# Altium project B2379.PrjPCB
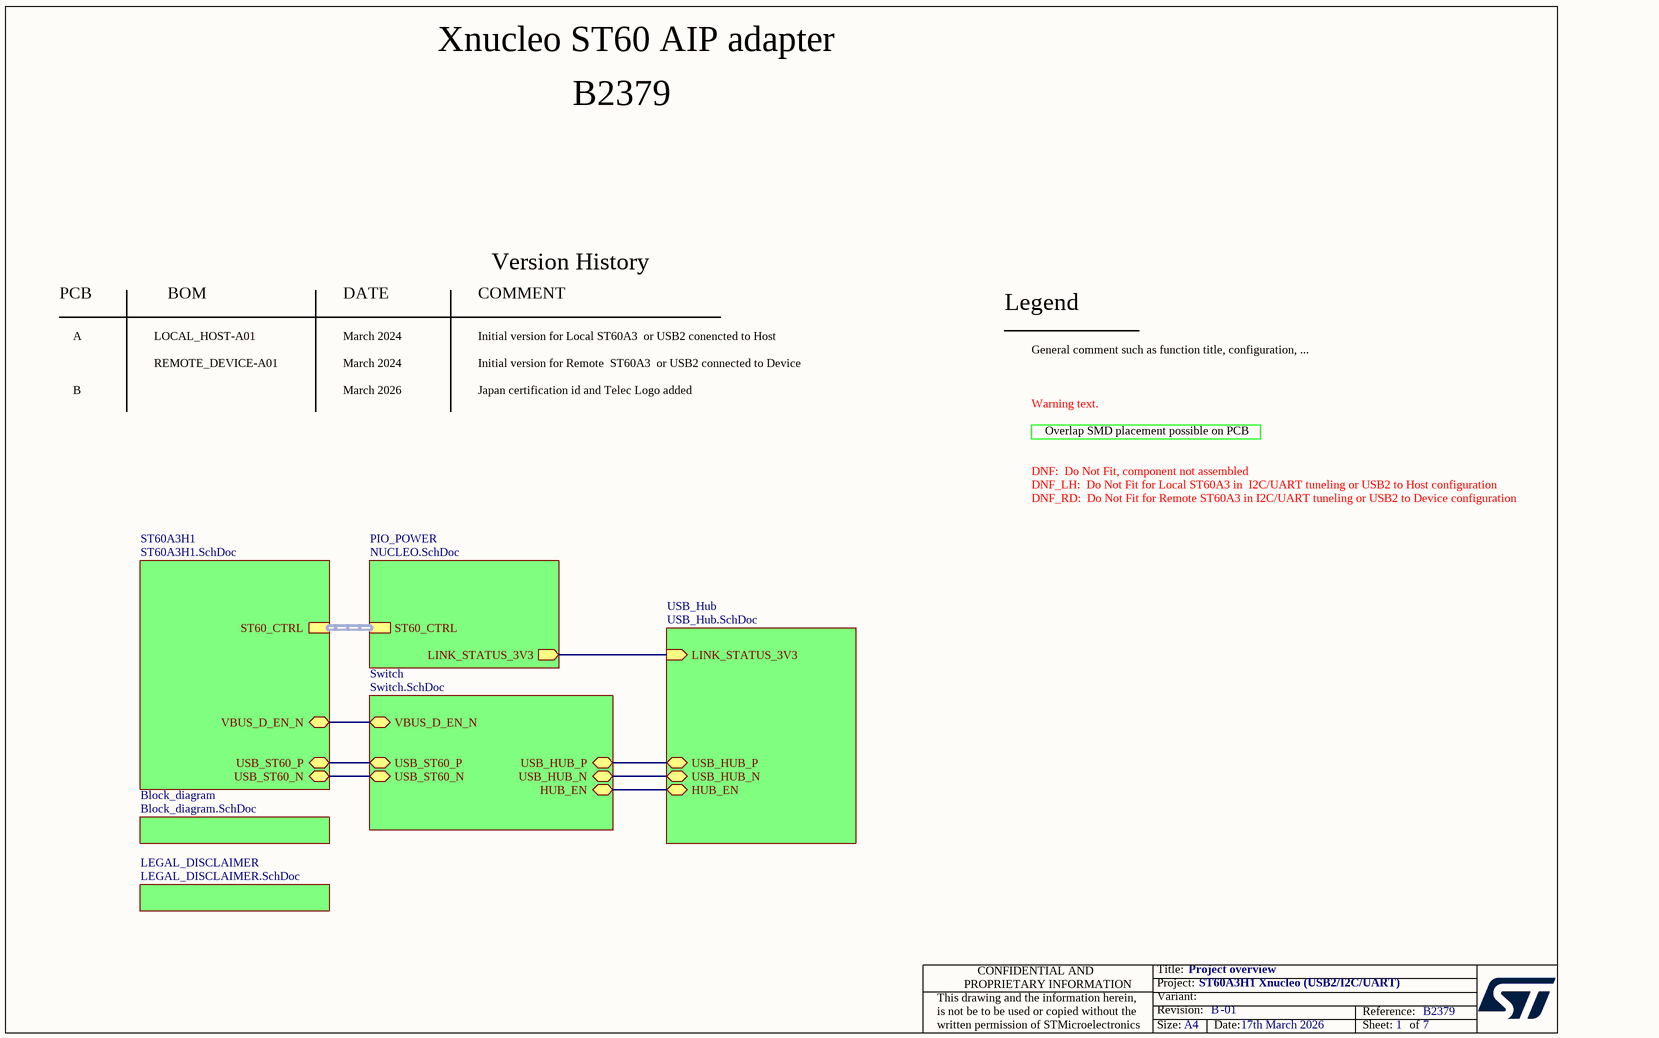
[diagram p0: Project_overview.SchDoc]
Board_Assembly_Revision: 01; Board_Document_Date: 17th March 2026; Board_Name: ST60A3H1 Xnucleo (USB2/I2C/UART); Board_PCB_Revision: B; Board_Reference: B2379
7 sheets, 182 parts. Net scope: hierarchical (ports join the sheet entries above them; power ports are global).
Board file: B2379.PcbDoc
Sheets:
  Project_overview.SchDoc
    ST60A3H1 = ST60A3H1.SchDoc
    Block_diagram = Block_diagram.SchDoc
    PIO_POWER = NUCLEO.SchDoc
    USB_Hub = USB_Hub.SchDoc
    LEGAL_DISCLAIMER = LEGAL_DISCLAIMER.SchDoc
    Switch = Switch.SchDoc

## Sheet Project_overview.SchDoc: Project overview
size A4; Date: Not used; ApprovedBy: Not used; CheckedBy: Not used; Author: Not used; CompanyName: STMicroelectronics; DrawnBy: Not used; Engineer: Not used; Organization: Not used; Address1: Not used; Address2: Not used; Address3: Not used; Address4: Not used; DocumentNumber: 1; Revision: Not used; SheetNumber: 1; SheetTotal: 7

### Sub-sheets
Block_diagram = Block_diagram.SchDoc: no entries
LEGAL_DISCLAIMER = LEGAL_DISCLAIMER.SchDoc: no entries
PIO_POWER = NUCLEO.SchDoc: ST60_CTRL (harness ST60_CTRL), LINK_STATUS_3V3 (out)
ST60A3H1 = ST60A3H1.SchDoc: USB_ST60_P (bidir), USB_ST60_N (bidir), ST60_CTRL (harness ST60_CTRL), VBUS_D_EN_N (bidir)
Switch = Switch.SchDoc: USB_ST60_P (bidir), USB_ST60_N (bidir), USB_HUB_N (bidir), USB_HUB_P (bidir), VBUS_D_EN_N (bidir), HUB_EN (bidir)
USB_Hub = USB_Hub.SchDoc: LINK_STATUS_3V3 (in), USB_HUB_N (bidir), USB_HUB_P (bidir), HUB_EN (bidir)

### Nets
HUB_EN: sheet USB_Hub/HUB_EN, sheet Switch/HUB_EN
LINK_STATUS_3V3: sheet PIO_POWER/LINK_STATUS_3V3, sheet USB_Hub/LINK_STATUS_3V3
USB_HUB_N: sheet USB_Hub/USB_HUB_N, sheet Switch/USB_HUB_N
USB_HUB_P: sheet USB_Hub/USB_HUB_P, sheet Switch/USB_HUB_P
USB_ST60_N: sheet ST60A3H1/USB_ST60_N, sheet Switch/USB_ST60_N
USB_ST60_P: sheet ST60A3H1/USB_ST60_P, sheet Switch/USB_ST60_P
VBUS_D_EN_N: sheet ST60A3H1/VBUS_D_EN_N, sheet Switch/VBUS_D_EN_N

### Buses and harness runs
harness sheet PIO_POWER/ST60_CTRL = sheet ST60A3H1/ST60_CTRL

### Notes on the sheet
- Xnucleo ST60 AIP adapter
- PCB
- BOM
- DATE
- COMMENT
- Version History
- Legend
- A
- LOCAL_HOST-A01
- REMOTE_DEVICE-A01
- March 2024
- Initial version for Local ST60A3  or USB2 conencted to Host
- Initial version for Remote  ST60A3  or USB2 connected to Device
- General comment such as function title, configuration, ...
- B
- March 2026
- Japan certification id and Telec Logo added
- Warning text.
- Overlap SMD placement possible on PCB
- DNF:  Do Not Fit, component not assembled
- DNF_LH:  Do Not Fit for Local ST60A3 in  I2C/UART tuneling or USB2 to Host configuration
- DNF_RD:  Do Not Fit for Remote ST60A3 in I2C/UART tuneling or USB2 to Device configuration

## Sheet ST60A3H1.SchDoc: ST60A3H1
size A4; DocumentNumber: 3; SheetNumber: 3; SheetTotal: 7
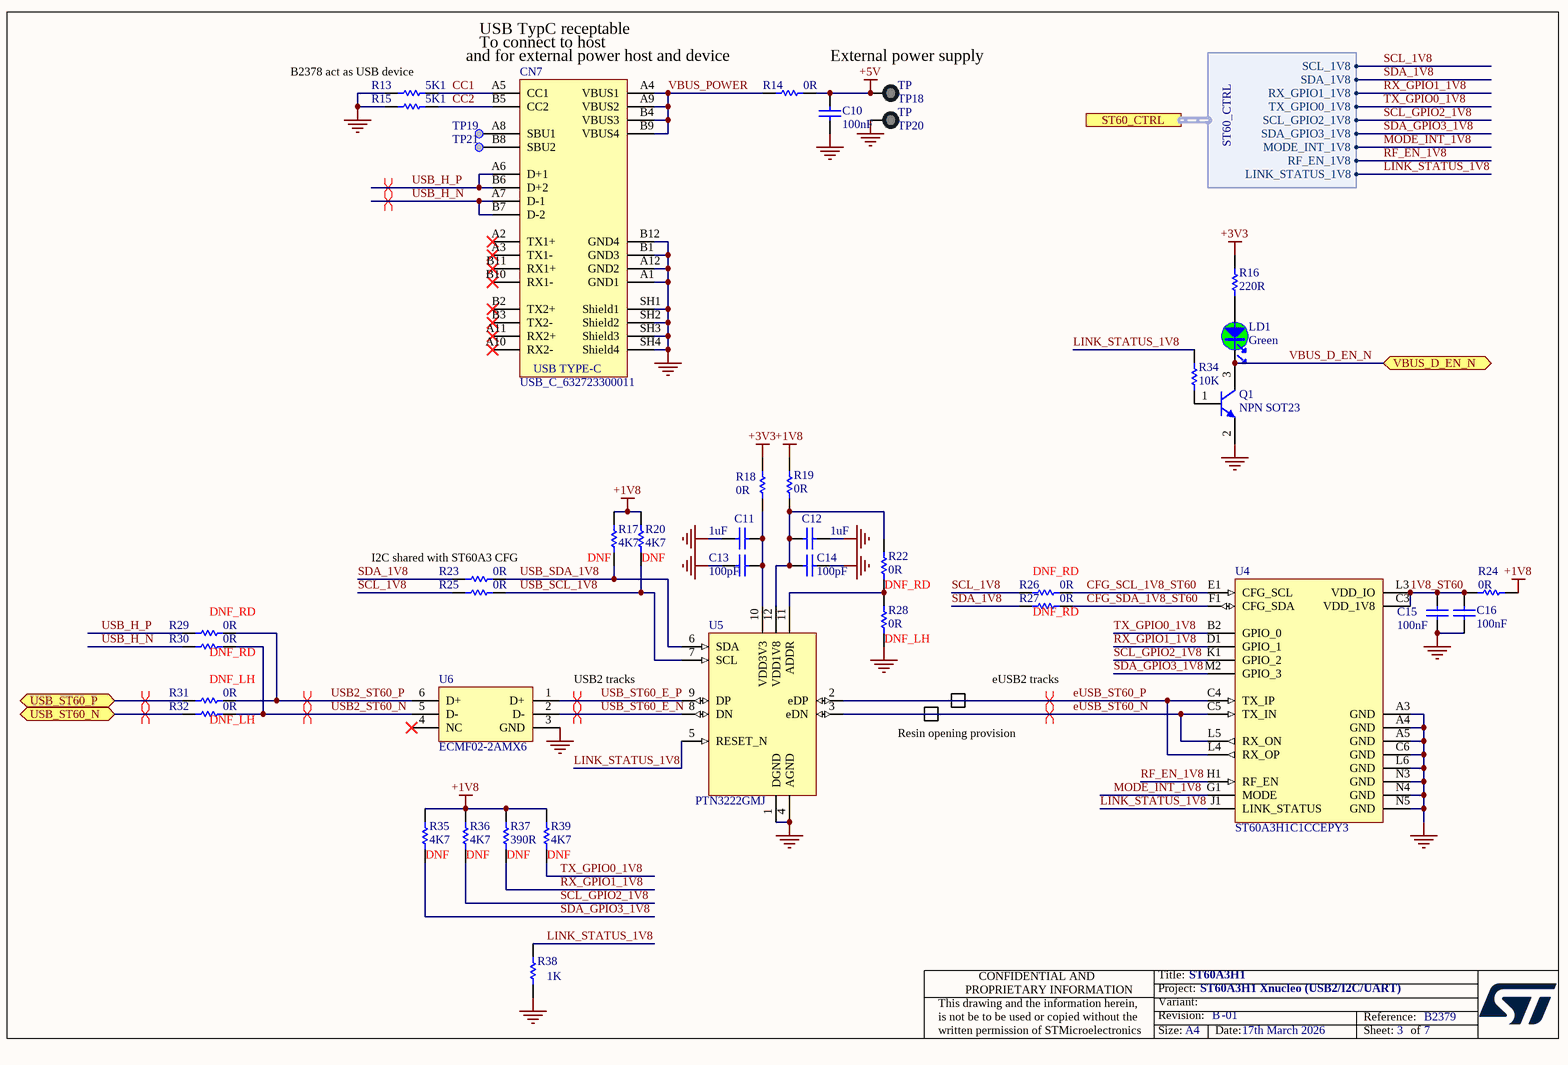
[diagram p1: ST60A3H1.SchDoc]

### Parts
C10  value 100nF  [C0402]  (hidden comment: Capacitor)
C11  value 1uF  [C0402]  (hidden comment: Capacitor)
C12  value 1uF  [C0402]  (hidden comment: Capacitor)
C13  value 100pF  [C0402]  (hidden comment: Capacitor)
C14  value 100pF  [C0402]  (hidden comment: Capacitor)
C15  value 100nF  [C0402]  (hidden comment: Capacitor)
C16  value 100nF  [C0402]  (hidden comment: Capacitor)
CN7  value USB_C_632723300011  [CON_USB-TYPEC_WE_632723300011]  (hidden comment: USB_TYPE_C_Receptacle)
LD1  value Green  [LED_0603_GREEN]  (hidden comment: LED_green)
Q1  value NPN SOT23  [NPN_SOT23]  (hidden comment: 9013-SOT23)
R13  value 5K1  [R0402]  (hidden comment: Resistor)
R14  value 0R  [SOLDER-BRIDGE_R0603-0R]  (hidden comment: Resistor)
R15  value 5K1  [R0402]  (hidden comment: Resistor)
R16  value 220R  [R0402]  (hidden comment: Resistor)
R17  value 4K7  [R0402]  (hidden comment: Resistor)
R18  value 0R  [R0402]  (hidden comment: Resistor)
R19  value 0R  [R0402]  (hidden comment: Resistor)
R20  value 4K7  [R0402]  (hidden comment: Resistor)
R22  value 0R  [SOLDER-BRIDGE_R0603-0R]  (hidden comment: Resistor)
R23  value 0R  [R0402]  (hidden comment: Resistor)
R24  value 0R  [R0402]  (hidden comment: Resistor)
R25  value 0R  [R0402]  (hidden comment: Resistor)
R26  value 0R  [SOLDER-BRIDGE_R0603-0R]  (hidden comment: Resistor)
R27  value 0R  [SOLDER-BRIDGE_R0603-0R]  (hidden comment: Resistor)
R28  value 0R  [SOLDER-BRIDGE_R0603-0R]  (hidden comment: Resistor)
R29  value 0R  [R0402_BGA]  (hidden comment: Resistor)
R30  value 0R  [R0402_BGA]  (hidden comment: Resistor)
R31  value 0R  [R0402_BGA]  (hidden comment: Resistor)
R32  value 0R  [R0402_BGA]  (hidden comment: Resistor)
R34  value 10K  [R0402]  (hidden comment: Resistor)
R35  value 4K7  [R0402]  (hidden comment: Resistor)
R36  value 4K7  [R0402]  (hidden comment: Resistor)
R37  value 390R  [R0402]  (hidden comment: Resistor)
R38  value 1K  [R0402]  (hidden comment: Resistor)
R39  value 4K7  [R0402]  (hidden comment: Resistor)
TP18  value TP  [TP_PTH_1MM_1P4MM]  (hidden comment: Test_Point_PTH_1mm_2mm)  (no BOM)
TP19  Test Point  [TP_SMD_1MM]  (value not drawn)  (no BOM)
TP20  value TP  [TP_PTH_1MM_1P4MM]  (hidden comment: Test_Point_PTH_1mm_2mm)  (no BOM)
TP21  Test Point  [TP_SMD_1MM]  (value not drawn)  (no BOM)
U4  value ST60A3H1C1CCEPY3  [ICC_VFBGA23_AiP_2P9X4P1_P040_B2310D]  (hidden comment: ST60A3G1)
U5  PTN3222GMJ  [ICC_XQFN12_1P75X2P2_P040_SOT2074-1]
U6  value ECMF02-2AMX6  [ESD_QFN-6L_1P7X1P5_P050]  (hidden comment: ​)

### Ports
ST60_CTRL (harness ST60_CTRL), USB_ST60_N (bidir), USB_ST60_P (bidir), VBUS_D_EN_N (bidir)

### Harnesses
ST60_CTRL: SCL_1V8, SDA_1V8, TX_GPIO0_1V8, RX_GPIO1_1V8, SCL_GPIO2_1V8, SDA_GPIO3_1V8, MODE_INT_1V8, RF_EN_1V8, LINK_STATUS_1V8

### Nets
+1V8: R17.2 R19.2 R20.2 R24.1 R35.2 R36.2 R37.2 R39.2
+3V3: R16.2 R18.2
+5V: C10.2 R14.2 TP18.1
GND: C10.1 C11.1 C12.2 C13.2 C14.2 C15.1 C16.2 CN7.A1(GND1) CN7.A12(GND2) CN7.B1(GND3) CN7.B12(GND4) CN7.SH1(Shield1) CN7.SH2(Shield2) CN7.SH3(Shield3) CN7.SH4(Shield4) Q1.2(E) R13.1 R15.1 R28.2 R38.1 TP20.1 U4.A3(GND) U4.A4(GND) U4.A5(GND) U4.C6(GND) U4.L6(GND) U4.N3(GND) U4.N4(GND) U4.N5(GND) U5.1(DGND) U5.4(AGND) U6.3(GND)
1V8_ST60: C15.2 C16.1 R24.2 U4.C3(VDD_1V8) U4.L3(VDD_IO)  [project net 1V8_ST60_3]
CC1: CN7.A5(CC1) R13.2  [project net CC1_3]
CC2: CN7.B5(CC2) R15.2  [project net CC2_3]
CFG_SCL_1V8_ST60: R26.2 U4.E1(CFG_SCL)  [project net CFG_SCL_1V8_ST60_3]
CFG_SDA_1V8_ST60: R27.2 U4.F1(CFG_SDA)  [project net CFG_SDA_1V8_ST60_3]
eUSB_ST60_N: U4.C5(TX_IN) U4.L5(RX_ON) U5.3(eDN)  [project net eUSB_ST60_N_3]
eUSB_ST60_P: U4.C4(TX_IP) U4.L4(RX_OP) U5.2(eDP)  [project net eUSB_ST60_P_3]
LINK_STATUS_1V8: R34.2 R38.2 U4.J1(LINK_STATUS) U5.5(RESET_N) ; port ST60_CTRL.LINK_STATUS_1V8
MODE_INT_1V8: U4.G1(MODE) ; port ST60_CTRL.MODE_INT_1V8
RF_EN_1V8: U4.H1(RF_EN) ; port ST60_CTRL.RF_EN_1V8
RX_GPIO1_1V8: R37.1 U4.D1(GPIO_1) ; port ST60_CTRL.RX_GPIO1_1V8
SCL_1V8: R25.1 R26.1 ; port ST60_CTRL.SCL_1V8
SCL_GPIO2_1V8: R36.1 U4.K1(GPIO_2) ; port ST60_CTRL.SCL_GPIO2_1V8
SDA_1V8: R23.1 R27.1 ; port ST60_CTRL.SDA_1V8
SDA_GPIO3_1V8: R35.1 U4.M2(GPIO_3) ; port ST60_CTRL.SDA_GPIO3_1V8
TX_GPIO0_1V8: R39.1 U4.B2(GPIO_0) ; port ST60_CTRL.TX_GPIO0_1V8
USB2_ST60_N: R30.2 R32.2 U6.5(D-)  [project net USB2_ST60_N_3]
USB2_ST60_P: R29.2 R31.2 U6.6(D+)  [project net USB2_ST60_P_3]
USB_H_N: CN7.A7(D-1) CN7.B7(D-2) R30.1  [project net USB_H_N_3]
USB_H_P: CN7.A6(D+1) CN7.B6(D+2) R29.1  [project net USB_H_P_3]
USB_SCL_1V8: R20.1 R25.2 U5.7(SCL)  [project net USB_SCL_1V8_3]
USB_SDA_1V8: R17.1 R23.2 U5.6(SDA)  [project net USB_SDA_1V8_3]
USB_ST60_E_N: U5.8(DN) U6.2(D-)  [project net USB_ST60_E_N_3]
USB_ST60_E_P: U5.9(DP) U6.1(D+)  [project net USB_ST60_E_P_3]
USB_ST60_N: R32.1 ; port USB_ST60_N
USB_ST60_P: R31.1 ; port USB_ST60_P
VBUS_D_EN_N: LD1.2 Q1.3(C) ; port VBUS_D_EN_N
VBUS_POWER: CN7.A4(VBUS1) CN7.A9(VBUS2) CN7.B4(VBUS3) CN7.B9(VBUS4) R14.1  [project net VBUS_POWER_3]
NetC11_2: C11.2 C13.1 R18.1 U5.10(VDD3V3)
NetC12_1: C12.1 C14.1 R19.1 R22.1 U5.12(VDD1V8)
NetCN7_A8: CN7.A8(SBU1) TP19.1
NetCN7_B8: CN7.B8(SBU2) TP21.1
NetLD1_1: LD1.1 R16.1
NetQ1_1: Q1.1(B) R34.1
NetR22_2: R22.2 R28.1 U5.11(ADDR)

Not connected (* = marked no-connect by the designer): CN7 A2(TX1+)* A3(TX1-)* A10(RX2-)* A11(RX2+)* B2(TX2+)* B3(TX2-)* B10(RX1-)* B11(RX1+)*; U6 4(NC)*

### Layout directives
differential pair; differential pair class 90 Ohms  Zdiff; rule Differential Pairs Routing [Pref Gap = 0.127mm    Min Gap  = 0.127mm    Max Gap  = 0.127mmPref Width = 0.19mm    Min Width  = 0.19mm    Max Width  = 0.19mm]: eUSB_ST60_N_3, eUSB_ST60_P_3, USB2_ST60_N_3, USB2_ST60_P_3, USB_H_N_3, USB_H_P_3, USB_ST60_E_N_3, USB_ST60_E_P_3, USB_ST60_N, USB_ST60_P

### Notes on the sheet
- USB TypC receptable
- (near CN7) To connect to host
- (near R13) B2378 act as USB device
- and for external power host and device
- External power supply
- (near R23) I2C shared with ST60A3 CFG
- (near R17) DNF
- (near R20) DNF
- (near R22) DNF_RD
- (near R26) DNF_RD
- (near R29) DNF_RD
- (near R30) DNF_RD
- (near R28) DNF_LH
- (near R27) DNF_RD
- (near R32) DNF_LH
- (near R31) DNF_LH
- (near U6) USB2 tracks
- eUSB2 tracks
- Resin opening provision
- (near R35) DNF
- (near R36) DNF
- (near R37) DNF
- (near R39) DNF

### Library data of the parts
C10 C15 C16 = MCD-00006: Capacitor, MLCC, 100nF, 16V, X7R, +/-10%, 0402, T=0.5mm; Part_Preference: Recommended; Manufacturer: YAGEO; Manufacturer_Part_Number: CC0402KRX7R7BB104; Partial_Alternate_Internal_Part_Number: MCD-03299; Order_Code_RS: 9402047; Component_Country_Of_Origin: China; ShowFields: YES; ID: 2474
C11 C12 = MCD-03432: Capacitor, MLCC, 1uF, 6.3V, X5R, +/- 10%, 0402, T=0.5mm; Part_Preference: Recommended; Manufacturer: MURATA; Manufacturer_Part_Number: GRM155R70J105KA12; Order_Code_RS: 113-8711; Component_Country_Of_Origin: China, Japan, Philippines, Singapore; ShowFields: YES; ID: 5548
C13 C14 = MCD-00205: Capacitor, MLCC, 100pF, 50V, NPO, +/-5%, 0402, T=0.5mm; Part_Preference: Recommended; Manufacturer: YAGEO; Manufacturer_Part_Number: CC0402JRNPO9BN101; Component_Country_Of_Origin: China; ShowFields: YES; ID: 2658
CN7 = MCD-02273: Connector_USB_TypeC, 24pins, RA, TH, T=1.9mm (USB certified); Part_Preference: Recommended; Manufacturer: WURTH ELEKTRONIK; Manufacturer_Part_Number: 632723300011; Full_Alternate_Internal_Part_Number: MCD-01108; Component_Country_Of_Origin: China; ShowFields: YES; ID: 4373
LD1 = MCD-02900: LED, Green, 2V, 20mA, 0603; Part_Type: Display; Part_Preference: Recommended; Manufacturer: EVERLIGHT; Manufacturer_Part_Number: 19-213SYGC/S530-E2/5T; Full_Alternate_Internal_Part_Number: MCD-00320; Partial_Alternate_Internal_Part_Number: MCD-00050; Component_Country_Of_Origin: China; ShowFields: YES; ID: 5016
Q1 = MCD-00073: NPN Bipolar Transistor; Part_Type: IC; Part_Preference: Recommended; Manufacturer: ON SEMICONDUCTOR; Manufacturer_Part_Number: BSR14; Partial_Alternate_Internal_Part_Number: MCD-01737, MCD-03305, , MCD-02988; Component_Country_Of_Origin: Unknown; ShowFields: YES; ID: 2519
R13 R15 = MCD-00333: Resistor, 5K1, 0402, +/-1%, 1/16W; Part_Preference: Recommended; Manufacturer: YAGEO; Manufacturer_Part_Number: RC0402FR-075K1L; Component_Country_Of_Origin: China; ShowFields: YES; ID: 2944
R14 R22 R26-R28 = MCD-00056: Resistor, 0R, 0603, +/-5%, 1/10W; Part_Preference: Recommended; Manufacturer: YAGEO; Manufacturer_Part_Number: RC0603JR-070RL; Order_Code_RS: 9233130RL; Component_Country_Of_Origin: China; ShowFields: YES; ID: 2536
R16 = MCD-00427: Resistor, 220R, 0402, +/-1%, 1/16W; Part_Preference: Recommended; Manufacturer: YAGEO; Manufacturer_Part_Number: RC0402FR-07220RL; Component_Country_Of_Origin: China; ShowFields: YES; ID: 2850
R17 R20 R35 R36 R39 = MCD-00065: Resistor, 4K7, 0402, +/-1%, 1/16W; Part_Preference: Recommended; Manufacturer: YAGEO; Manufacturer_Part_Number: RC0402FR-074K7L; Partial_Alternate_Internal_Part_Number: MCD-03300; Order_Code_RS: 9239316; Component_Country_Of_Origin: China; ShowFields: YES; ID: 2526
R18 R19 R23-R25 R29-R32 = MCD-00052: Resistor, 0R, 0402, +/-5%, 1/16W; Part_Preference: Recommended; Manufacturer: YAGEO; Manufacturer_Part_Number: RC0402JR-070RL; Order_Code_RS: 9232516RL; Component_Country_Of_Origin: China; ShowFields: YES; ID: 2540
R34 = MCD-00053: Resistor, 10K, 0402, +/-1%, 1/16W; BMS_Part_Number: 9131590; Part_Preference: Recommended; Manufacturer: YAGEO; Manufacturer_Part_Number: RC0402FR-0710KL; Order_Code_RS: 9239359; Component_Country_Of_Origin: China; ShowFields: YES; ID: 2539
R37 = MCD-00467: Resistor, 390R, 0402, +/-1%, 1/16W; Part_Preference: Recommended; Manufacturer: YAGEO; Manufacturer_Part_Number: RC0402FR-07390RL; Component_Country_Of_Origin: China; ShowFields: YES; ID: 2812
R38 = MCD-00061: Resistor, 1K, 0402, +/-1%,1/16W; Part_Preference: Recommended; Manufacturer: YAGEO; Manufacturer_Part_Number: RC0402FR-071KL; Order_Code_RS: 9239235; Component_Country_Of_Origin: China; ShowFields: YES; ID: 2532
TP18 TP20 = MCD-03401: Test Point trought hole 1mm/1.4mm; Part_Type: Misc; Part_Preference: Recommended; Component_Country_Of_Origin: Unknown; ShowFields: YES; ID: 5517
TP19 TP21 = MCD-00074: Test Point 1mm; Part_Type: Misc; Part_Preference: Recommended; ShowFields: YES; ID: 2518; Component_Country_Of_Origin: Unknown
U4 = MCD-03857: Transceiver, 60GHz, V-band contactless connectivity, with eUSB2, UART, GPIO, or I2C tunneling, VDDIO 1V8; Part_Type: IC; Part_Preference: Recommended; Manufacturer: STMICROELECTRONICS; Component_Country_Of_Origin: Taiwan; ShowFields: YES; ID: 5973
U5 = MCD-03404: 1-port PTN3222 implements Repeater mode (eUSB2 to USB2 redriver); Part_Type: IC; Part_Preference: Recommended; Manufacturer: NXP; Component_Country_Of_Origin: Unknown; ShowFields: YES; ID: 5520
U6 = MCD-00649: Diode, ESD protection, 1V5, 100nA, 6V, QFN-6; Manufacturer: STMICROELECTRONICS; BMS_Part_Number: 9151138; Part_Preference: Recommended; Manufacturer_HQ_COO: EU; Order_Code_RS: 880-5276; Component_Country_Of_Origin: China; ShowFields: YES; ID: 3094

## Sheet Block_diagram.SchDoc: Block Diagram
size A4; Date: Not used; ApprovedBy: Not used; CheckedBy: Not used; Author: Not used; CompanyName: STMicroelectronics; DrawnBy: Not used; Engineer: Not used; Organization: Not used; Address1: Not used; Address2: Not used; Address3: Not used; Address4: Not used; DocumentNumber: 2; Revision: Not used; SheetNumber: 2; SheetTotal: 7
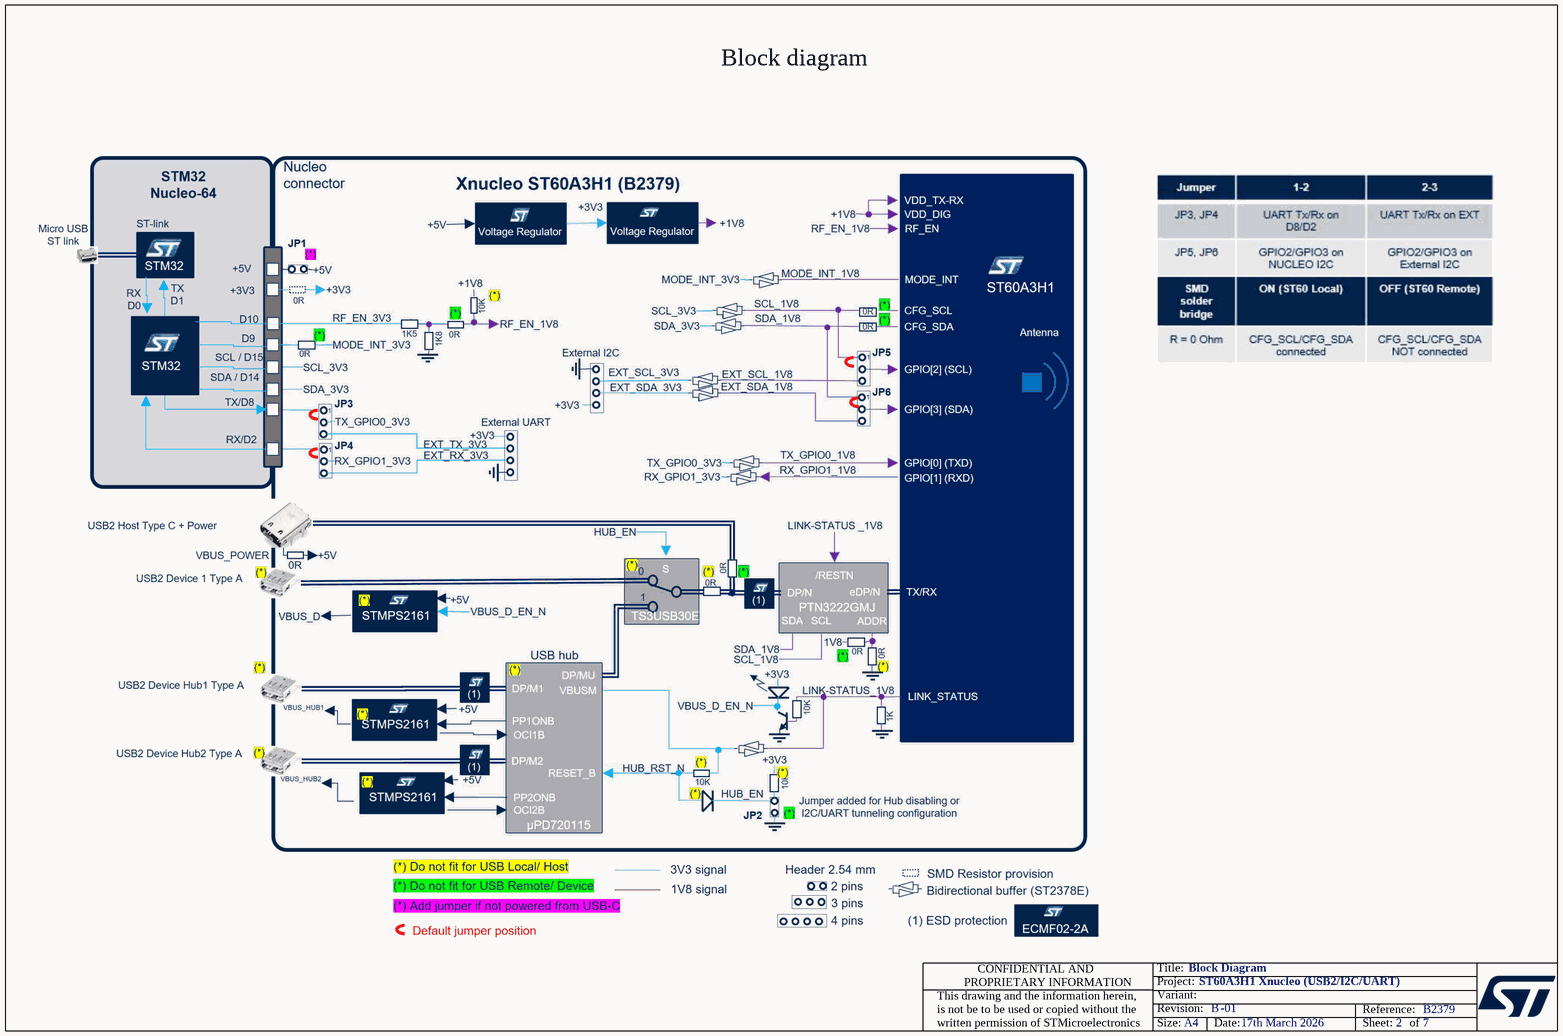
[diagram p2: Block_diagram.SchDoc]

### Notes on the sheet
- Block diagram

## Sheet NUCLEO.SchDoc: NUCLEO
size A4; DocumentNumber: 4; SheetNumber: 4; SheetTotal: 7
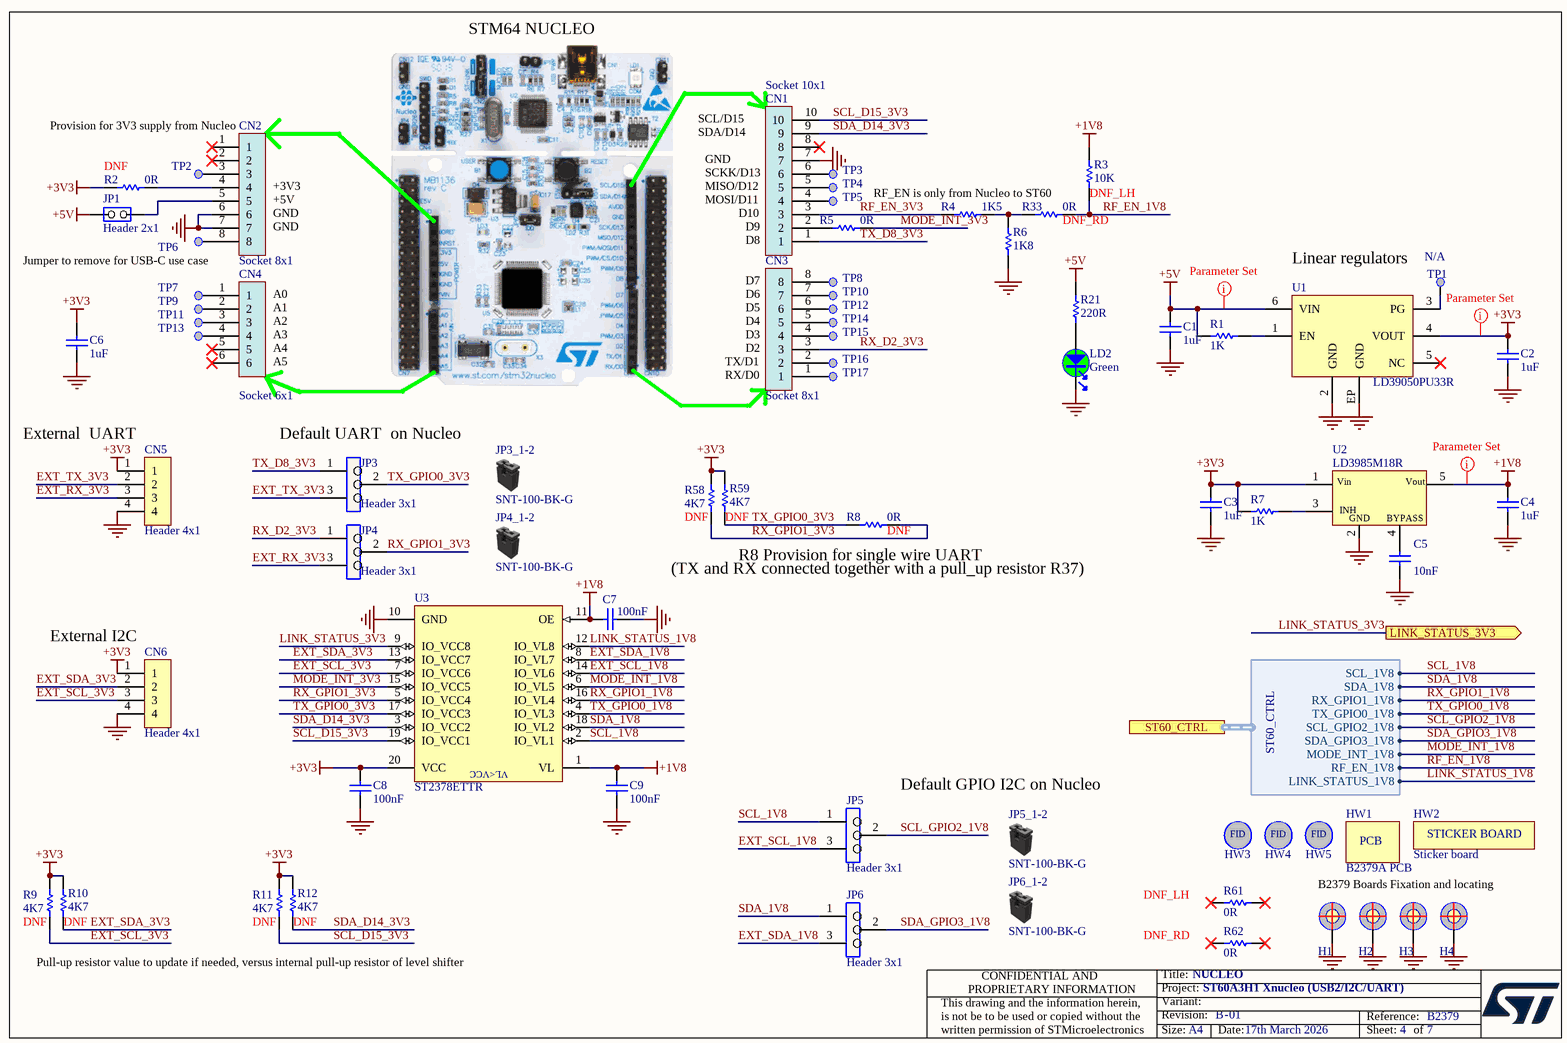
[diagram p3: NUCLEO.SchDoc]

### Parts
C1  value 1uF  [C0402]  (hidden comment: Capacitor)
C2  value 1uF  [C0402]  (hidden comment: Capacitor)
C3  value 1uF  [C0402]  (hidden comment: Capacitor)
C4  value 1uF  [C0402]  (hidden comment: Capacitor)
C5  value 10nF  [C0402]  (hidden comment: Capacitor)
C6  value 1uF  [C0402]  (hidden comment: Capacitor)
C7  value 100nF  [C0402]  (hidden comment: Capacitor)
C8  value 100nF  [C0402]  (hidden comment: Capacitor)
C9  value 100nF  [C0402]  (hidden comment: Capacitor)
CN1  Socket 10x1  [CON_SAMTEC_SSQ-110-03-F-S]
CN2  Socket 8x1  [CON_SAMTEC_SSQ-108-03-F-S]
CN3  Socket 8x1  [CON_SAMTEC_SSQ-108-03-F-S]
CN4  Socket 6x1  [CON_SAMTEC_SSQ-106-03-F-S]
CN5  Header 4x1  [CON_SAMTEC_TSW-104-07-G-S]
CN6  Header 4x1  [CON_SAMTEC_TSW-104-07-G-S]
H1  POSITION HOLE  [NPTH_300]  (value not drawn)  (no BOM)
H2  POSITION HOLE  [NPTH_300]  (value not drawn)  (no BOM)
H3  POSITION HOLE  [NPTH_300]  (value not drawn)  (no BOM)
H4  POSITION HOLE  [NPTH_300]  (value not drawn)  (no BOM)
HW1  B2379A PCB  (mechanical)
HW2  value Sticker board  [STICKER_Board_15X5]  (hidden comment: STICKER_BOARD)  (no BOM)
HW3  FiducialPad  [MIRE_PLACE_SMD_0P8MM]  (value not drawn)  (no BOM)
HW4  FiducialPad  [MIRE_PLACE_SMD_0P8MM]  (value not drawn)  (no BOM)
HW5  FiducialPad  [MIRE_PLACE_SMD_0P8MM]  (value not drawn)  (no BOM)
JP1  value Header 2x1  [CON_SAMTEC_TSW-102-07-G-S]  (hidden comment: Jumper_Header 2x1)
JP3  value Header 3x1  [CON_SAMTEC_TSW-103-07-F-S]  (hidden comment: Jumper_Header 3x1)
JP3_1-2  value SNT-100-BK-G  (hidden comment: Shunt Black 2.54mm)  (mechanical)
JP4  value Header 3x1  [CON_SAMTEC_TSW-103-07-F-S]  (hidden comment: Jumper_Header 3x1)
JP4_1-2  value SNT-100-BK-G  (hidden comment: Shunt Black 2.54mm)  (mechanical)
JP5  value Header 3x1  [CON_SAMTEC_TSW-103-07-F-S]  (hidden comment: Jumper_Header 3x1)
JP5_1-2  value SNT-100-BK-G  (hidden comment: Shunt Black 2.54mm)  (mechanical)
JP6  value Header 3x1  [CON_SAMTEC_TSW-103-07-F-S]  (hidden comment: Jumper_Header 3x1)
JP6_1-2  value SNT-100-BK-G  (hidden comment: Shunt Black 2.54mm)  (mechanical)
LD2  value Green  [LED_0603_GREEN]  (hidden comment: LED_green)
R1  value 1K  [R0402]  (hidden comment: Resistor)
R2  value 0R  [SOLDER-BRIDGE_R0603-0R]  (hidden comment: Resistor)
R3  value 10K  [R0402]  (hidden comment: Resistor)
R4  value 1K5  [R0402]  (hidden comment: Resistor)
R5  value 0R  [SOLDER-BRIDGE_R0603-0R]  (hidden comment: Resistor)
R6  value 1K8  [R0402]  (hidden comment: Resistor)
R7  value 1K  [R0402]  (hidden comment: Resistor)
R8  value 0R  [SOLDER-BRIDGE_R0603-0R]  (hidden comment: Resistor)
R9  value 4K7  [R0402]  (hidden comment: Resistor)
R10  value 4K7  [R0402]  (hidden comment: Resistor)
R11  value 4K7  [R0402]  (hidden comment: Resistor)
R12  value 4K7  [R0402]  (hidden comment: Resistor)
R21  value 220R  [R0402]  (hidden comment: Resistor)
R33  value 0R  [SOLDER-BRIDGE_R0603-0R]  (hidden comment: Resistor)
R58  value 4K7  [R0402]  (hidden comment: Resistor)
R59  value 4K7  [R0402]  (hidden comment: Resistor)
R61  value 0R  [SOLDER-BRIDGE_R0603-0R]  (hidden comment: Resistor)
R62  value 0R  [SOLDER-BRIDGE_R0603-0R]  (hidden comment: Resistor)
TP1  Test Point  [TP_SMD_0-6MM]  (value not drawn)  (no BOM)
TP2  Test Point  [TP_SMD_0-6MM]  (value not drawn)  (no BOM)
TP3  Test Point  [TP_SMD_0-6MM]  (value not drawn)  (no BOM)
TP4  Test Point  [TP_SMD_0-6MM]  (value not drawn)  (no BOM)
TP5  Test Point  [TP_SMD_0-6MM]  (value not drawn)  (no BOM)
TP6  Test Point  [TP_SMD_0-6MM]  (value not drawn)  (no BOM)
TP7  Test Point  [TP_SMD_0-6MM]  (value not drawn)  (no BOM)
TP8  Test Point  [TP_SMD_0-6MM]  (value not drawn)  (no BOM)
TP9  Test Point  [TP_SMD_0-6MM]  (value not drawn)  (no BOM)
TP10  Test Point  [TP_SMD_0-6MM]  (value not drawn)  (no BOM)
TP11  Test Point  [TP_SMD_0-6MM]  (value not drawn)  (no BOM)
TP12  Test Point  [TP_SMD_0-6MM]  (value not drawn)  (no BOM)
TP13  Test Point  [TP_SMD_0-6MM]  (value not drawn)  (no BOM)
TP14  Test Point  [TP_SMD_0-6MM]  (value not drawn)  (no BOM)
TP15  Test Point  [TP_SMD_0-6MM]  (value not drawn)  (no BOM)
TP16  Test Point  [TP_SMD_0-6MM]  (value not drawn)  (no BOM)
TP17  Test Point  [TP_SMD_0-6MM]  (value not drawn)  (no BOM)
U1  LD39050PU33R  [ICC_DFN6-EPAD_3X3_P095]
U2  LD3985M18R  [REG_SOT23-5L]
U3  ST2378ETTR  [ICC_TSSOP20_6P50X4P40_P065]

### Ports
LINK_STATUS_3V3 (out), ST60_CTRL (harness ST60_CTRL)

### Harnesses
ST60_CTRL: SCL_1V8, SDA_1V8, TX_GPIO0_1V8, RX_GPIO1_1V8, SCL_GPIO2_1V8, SDA_GPIO3_1V8, MODE_INT_1V8, RF_EN_1V8, LINK_STATUS_1V8

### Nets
+1V8: C4.2 C7.1 C9.2 R3.1 U2.5(Vout) U3.1(VL) U3.11(OE)
+3V3: C2.2 C3.2 C6.2 C8.2 CN5.1 CN6.1 R2.1 R7.1 R9.2 R10.2 R11.2 R12.2 R58.2 R59.2 U1.4(VOUT) U2.1(Vin) U3.20(VCC)
+5V: C1.2 JP1.1(COMMON) R1.1 R21.2 U1.6(VIN)
GND: C1.1 C2.1 C3.1 C4.1 C5.1 C6.1 C7.2 C8.1 C9.1 CN1.7 CN2.6 CN2.7 CN5.4 CN6.4 H1.1 H2.1 H3.1 H4.1 LD2.2 R6.1 U1.2(GND) U1.EP(GND) U2.2(GND) U3.10(GND)
EXT_RX_3V3: CN5.3 JP4.3  [project net EXT_RX_3V3_4]
EXT_SCL_1V8: JP5.3 U3.14(IO_VL6)  [project net EXT_SCL_1V8_4]
EXT_SCL_3V3: CN6.3 R9.1 U3.7(IO_VCC6)  [project net EXT_SCL_3V3_4]
EXT_SDA_1V8: JP6.3 U3.8(IO_VL7)  [project net EXT_SDA_1V8_4]
EXT_SDA_3V3: CN6.2 R10.1 U3.13(IO_VCC7)  [project net EXT_SDA_3V3_4]
EXT_TX_3V3: CN5.2 JP3.3  [project net EXT_TX_3V3_4]
LINK_STATUS_1V8: U3.12(IO_VL8) ; port ST60_CTRL.LINK_STATUS_1V8
LINK_STATUS_3V3: U3.9(IO_VCC8) ; port LINK_STATUS_3V3
MODE_INT_1V8: U3.6(IO_VL5) ; port ST60_CTRL.MODE_INT_1V8
MODE_INT_3V3: R5.2 U3.15(IO_VCC5)  [project net MODE_INT_3V3_4]
RF_EN_1V8: R3.2 R33.2 ; port ST60_CTRL.RF_EN_1V8
RF_EN_3V3: CN1.3 R4.1  [project net RF_EN_3V3_4]
RX_D2_3V3: CN3.3 JP4.1  [project net RX_D2_3V3_4]
RX_GPIO1_1V8: U3.16(IO_VL4) ; port ST60_CTRL.RX_GPIO1_1V8
RX_GPIO1_3V3: JP4.2 R8.2 R58.1 U3.5(IO_VCC4)  [project net RX_GPIO1_3V3_4]
SCL_1V8: JP5.1 U3.2(IO_VL1) ; port ST60_CTRL.SCL_1V8
SCL_D15_3V3: CN1.10 R11.1 U3.19(IO_VCC1)  [project net SCL_D15_3V3_4]
SCL_GPIO2_1V8: JP5.2 ; port ST60_CTRL.SCL_GPIO2_1V8
SDA_1V8: JP6.1 U3.18(IO_VL2) ; port ST60_CTRL.SDA_1V8
SDA_D14_3V3: CN1.9 R12.1 U3.3(IO_VCC2)  [project net SDA_D14_3V3_4]
SDA_GPIO3_1V8: JP6.2 ; port ST60_CTRL.SDA_GPIO3_1V8
TX_D8_3V3: CN1.1 JP3.1  [project net TX_D8_3V3_4]
TX_GPIO0_1V8: U3.4(IO_VL3) ; port ST60_CTRL.TX_GPIO0_1V8
TX_GPIO0_3V3: JP3.2 R8.1 R59.1 U3.17(IO_VCC3)  [project net TX_GPIO0_3V3_4]
NetC5_2: C5.2 U2.4(BYPASS)
NetCN1_2: CN1.2 R5.1
NetCN1_4: CN1.4 TP5.1
NetCN1_5: CN1.5 TP4.1
NetCN1_6: CN1.6 TP3.1
NetCN2_3: CN2.3 TP2.1
NetCN2_4: CN2.4 R2.2
NetCN2_5: CN2.5 JP1.2(NO)
NetCN2_8: CN2.8 TP6.1
NetCN3_1: CN3.1 TP17.1
NetCN3_2: CN3.2 TP16.1
NetCN3_4: CN3.4 TP15.1
NetCN3_5: CN3.5 TP14.1
NetCN3_6: CN3.6 TP12.1
NetCN3_7: CN3.7 TP10.1
NetCN3_8: CN3.8 TP8.1
NetCN4_1: CN4.1 TP7.1
NetCN4_2: CN4.2 TP9.1
NetCN4_3: CN4.3 TP11.1
NetCN4_4: CN4.4 TP13.1
NetLD2_1: LD2.1 R21.1
NetR1_2: R1.2 U1.1(EN)
NetR4_2: R4.2 R6.2 R33.1
NetR7_2: R7.2 U2.3(CE)
NetTP1_1: TP1.1 U1.3(PG)

Not connected (* = marked no-connect by the designer): CN1 8*; CN2 1* 2*; CN4 5* 6*; R61 1* 2*; R62 1* 2*; U1 5(NC)*

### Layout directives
rule Width Constraint [Pref Width = 0.5mm    Min Width = 0.35mm    Max Width = 1mm]: +5V
rule Width Constraint [Pref Width = 0.4mm    Min Width = 0.009mm    Max Width = 1mm]: +3V3
rule Width Constraint [Pref Width = 0.5mm    Min Width = 0.25mm    Max Width = 0.45mm]: +1V8

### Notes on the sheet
- STM64 NUCLEO
- (near CN1) SCL/D15
- (near CN2) Provision for 3V3 supply from Nucleo
- (near R2) DNF
- (near CN1) SDA/D14
- GND
- (near CN1) SCKK/D13
- (near CN2) +3V3
- (near CN2) GND
- (near CN2) +5V
- (near CN1) MISO/D12
- (near CN1) MOSI/D11
- (near CN1) D10
- (near CN1) D9
- D8
- RF_EN is only from Nucleo to ST60
- (near R33) DNF_RD
- (near R3) DNF_LH
- Jumper to remove for USB-C use case
- (near CN4) A0
- (near CN4) A1
- D7
- (near CN3) D6
- (near CN3) D5
- (near TP1) Linear regulators
- (near CN4) A2
- (near CN4) A3
- (near CN4) A4
- (near CN4) A5
- (near CN3) TX/D1
- (near CN3) RX/D0
- (near CN3) D4
- (near CN3) D3
- (near CN3) D2
- (near CN5) External  UART
- Default UART  on Nucleo
- (near R58) DNF
- (near R59) DNF
- (TX and RX connected together with a pull_up resistor R37)
- (near R8) R8 Provision for single wire UART
- (near R8) DNF
- (near CN6) External I2C
- (near JP5_1-2) Default GPIO I2C on Nucleo
- (near R9) DNF
- (near R10) DNF
- (near R11) DNF
- (near R12) DNF
- DNF_LH
- B2379 Boards Fixation and locating
- Pull-up resistor value to update if needed, versus internal pull-up resistor of level shifter
- DNF_RD

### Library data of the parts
C1-C4 C6 = MCD-03432: as C11 on sheet ST60A3H1
C5 = MCD-02198: Capacitor, MLCC, 10nF, 50V, X7R, +/-10%, 0402, T=0.5mm; Part_Preference: Recommended; Manufacturer: YAGEO; Manufacturer_Part_Number: CC0402KRX7R9BB103; Order_Code_RS: 6169644; Component_Country_Of_Origin: China; ShowFields: YES; ID: 4298
C7-C9 = MCD-00006: as C10 on sheet ST60A3H1
CN1 = MCD-02625: Socket, 10x1, 2.54mm, VR, TH, T=8.51mm/10mm; Part_Type: Connector; Part_Preference: Recommended; Manufacturer: SAMTEC; Manufacturer_Part_Number: SSQ-110-03-F-S; Partial_Alternate_Internal_Part_Number: MCD-03730, MCD-03784; Order_Code_RS: 154-8308; Component_Country_Of_Origin: China, Costa Rica, Malaysia, USA, Vietnam; ShowFields: YES; ID: 4731
CN2 CN3 = MCD-02624: Socket, 8x1, 2.54mm, VR, TH, T=8.51mm/10mm; Part_Type: Connector; Part_Preference: Recommended; Manufacturer: SAMTEC; Manufacturer_Part_Number: SSQ-108-03-F-S; Partial_Alternate_Internal_Part_Number: MCD-03729, MCD-03785; Order_Code_RS: 180-0395; Component_Country_Of_Origin: China, Costa Rica, Malaysia, USA, Vietnam; ShowFields: YES; ID: 4730
CN4 = MCD-02623: Socket, 6x1, 2.54mm, VR, TH, T=8.51mm/10mm; Part_Type: Connector; Part_Preference: Recommended; Manufacturer: SAMTEC; Manufacturer_Part_Number: SSQ-106-03-F-S; Partial_Alternate_Internal_Part_Number: MCD-03728, MCD-02623; Order_Code_RS: 180-0379; Component_Country_Of_Origin: China, Costa Rica, Malaysia, USA, Vietnam; ShowFields: YES; ID: 4729
CN5 CN6 = MCD-00029: Header, 4x1, 2.54mm, VR, TH, T=5.84mm/2.54mm; Part_Type: Connector; Part_Preference: Recommended; Manufacturer: SAMTEC; Manufacturer_Part_Number: TSW-104-07-G-S; Order_Code_RS: 2667450; Component_Country_Of_Origin: China, Costa Rica, Malaysia, USA, Vietnam; ShowFields: YES; ID: 2487
H1-H4 = RFC-00044: POSITION HOLE C3R0D3R0; Part_Type: Misc; Part_Preference: Recommended; Value: NPTH; Initial_Board_Reference: B2379; Requester_Name: Sebastien GILLES; ID: 36; Item Type: Item; Path: teams/HWBoards/Lists/RFC Part 2
HW1 = PCB_mb1263: PCB_B2379A; Fitted: YES; Ordered_By: Subcon
HW2 = MCD-02192: Sticker board 15x5 mm; Part_Type: Misc; Part_Preference: Recommended; ShowFields: YES; ID: 4292; Component_Country_Of_Origin: Unknown
HW3-HW5 = MCD-03135: Fiducial Pad, 0.8mm; Part_Type: Misc; Part_Preference: Recommended; ShowFields: YES; ID: 5251; Component_Country_Of_Origin: Unknown
JP1 = MCD-00045: Header, 2x1, 2.54mm, VR, TH, T=5.84mm/2.54mm; Part_Type: Connector; Part_Preference: Recommended; Manufacturer: SAMTEC; Manufacturer_Part_Number: TSW-102-07-G-S; Full_Alternate_Internal_Part_Number: MCD-02390; Partial_Alternate_Internal_Part_Number: MCD-02957, MCD-03720; Order_Code_RS: 2505044; Component_Country_Of_Origin: China, Costa Rica, Malaysia, USA, Vietnam; ShowFields: YES; ID: 2545
JP3-JP6 = MCD-00111: Header, 3x1, 2.54mm, VR, TH, T=5.84mm/2.54mm; Part_Type: Connector; Part_Preference: Recommended; Manufacturer: SAMTEC; Manufacturer_Part_Number: TSW-103-07-F-S; Order_Code_RS: 161-2248; Component_Country_Of_Origin: China, Costa Rica, Malaysia, USA, Vietnam; ShowFields: YES; ID: 2760
JP3_1-2 JP4_1-2 JP5_1-2 JP6_1-2 = MCD-00122: Shunt, 2.54mm, Black, 4.3A, 6.1mm, 5mR; Part_Type: Misc; Part_Preference: Recommended; Manufacturer: SAMTEC; Full_Alternate_Internal_Part_Number: MCD-00043; Partial_Alternate_Internal_Part_Number: MCD-01849; Order_Code_RS: 158-7784; Component_Country_Of_Origin: China, Costa Rica, Malaysia, USA, Vietnam; ShowFields: YES; ID: 2749
LD2 = MCD-02900: as LD1 on sheet ST60A3H1
R1 R7 = MCD-00061: as R38 on sheet ST60A3H1
R2 R5 R8 R33 R61 R62 = MCD-00056: as R14 on sheet ST60A3H1
R3 = MCD-00053: as R34 on sheet ST60A3H1
R4 = MCD-00068: Resistor, 1K5, 0402, +/-1%, 1/16W; Part_Preference: Recommended; Manufacturer: YAGEO; Manufacturer_Part_Number: RC0402FR-071K5L; Order_Code_RS: 9239251; Component_Country_Of_Origin: China; ShowFields: YES; ID: 2524
R6 = MCD-00409: Resistor, 1K8, 0402, +/-1%, 1/16W; Part_Preference: Recommended; Manufacturer: YAGEO; Manufacturer_Part_Number: RC0402FR-071K8L; Component_Country_Of_Origin: China; ShowFields: YES; ID: 2871
R9-R12 R58 R59 = MCD-00065: as R17 on sheet ST60A3H1
R21 = MCD-00427: as R16 on sheet ST60A3H1
TP1 = MCD-00631: Test Point 0.6mm; Part_Type: Misc; Part_Preference: Recommended; ShowFields: YES; ID: 3108; Component_Country_Of_Origin: Unknown
TP2-TP17 = MCD-00631: Test Point 0.6mm; Part_Type: Misc; Part_Preference: Recommended; Component_Country_Of_Origin: Unknown; ShowFields: YES; ID: 3108
U1 = MCD-00215: LDO, 500mA, Low quiescent current and low noise voltage regulator; BMS_Part_Number: 9176126; Part_Type: IC; Part_Preference: Recommended; Manufacturer: STMICROELECTRONICS; Component_Country_Of_Origin: Malaysia; ShowFields: YES; ID: 2654; Order_Code_RS: 196-1948
U2 = MCD-00078: LDO, Ultra low drop and low noise BiCMOS voltage regulators; BMS_Part_Number: 9176159; Part_Type: IC; Part_Preference: Recommended; Manufacturer: STMICROELECTRONICS; Manufacturer_HQ_COO: EU; Component_Country_Of_Origin: Malaysia; ShowFields: YES; ID: 2516; Order_Code_RS: 686-8830
U3 = MCD-03858: Translator, 8-bit, dual supply 1.71 V to 5.5 V, I/O VCC +/-15 kV ESD protection; Part_Type: IC; Part_Preference: Recommended; Manufacturer: STMICROELECTRONICS; Order_Code_RS: 880-5389; ShowFields: YES; ID: 5974; Component_Country_Of_Origin: Philippines

## Sheet USB_Hub.SchDoc: Hub
size A4; Project: STM32MP15-DISCO PI; Date: Not used; ApprovedBy: Not used; CheckedBy: Not used; Author: Not used; CompanyName: STMicroelectronics; DrawnBy: Not used; Engineer: Not used; Organization: Not used; Address1: Not used; Address2: Not used; Address3: Not used; Address4: Not used; DocumentNumber: 6; Revision: Not used; SheetNumber: 6; SheetTotal: 7
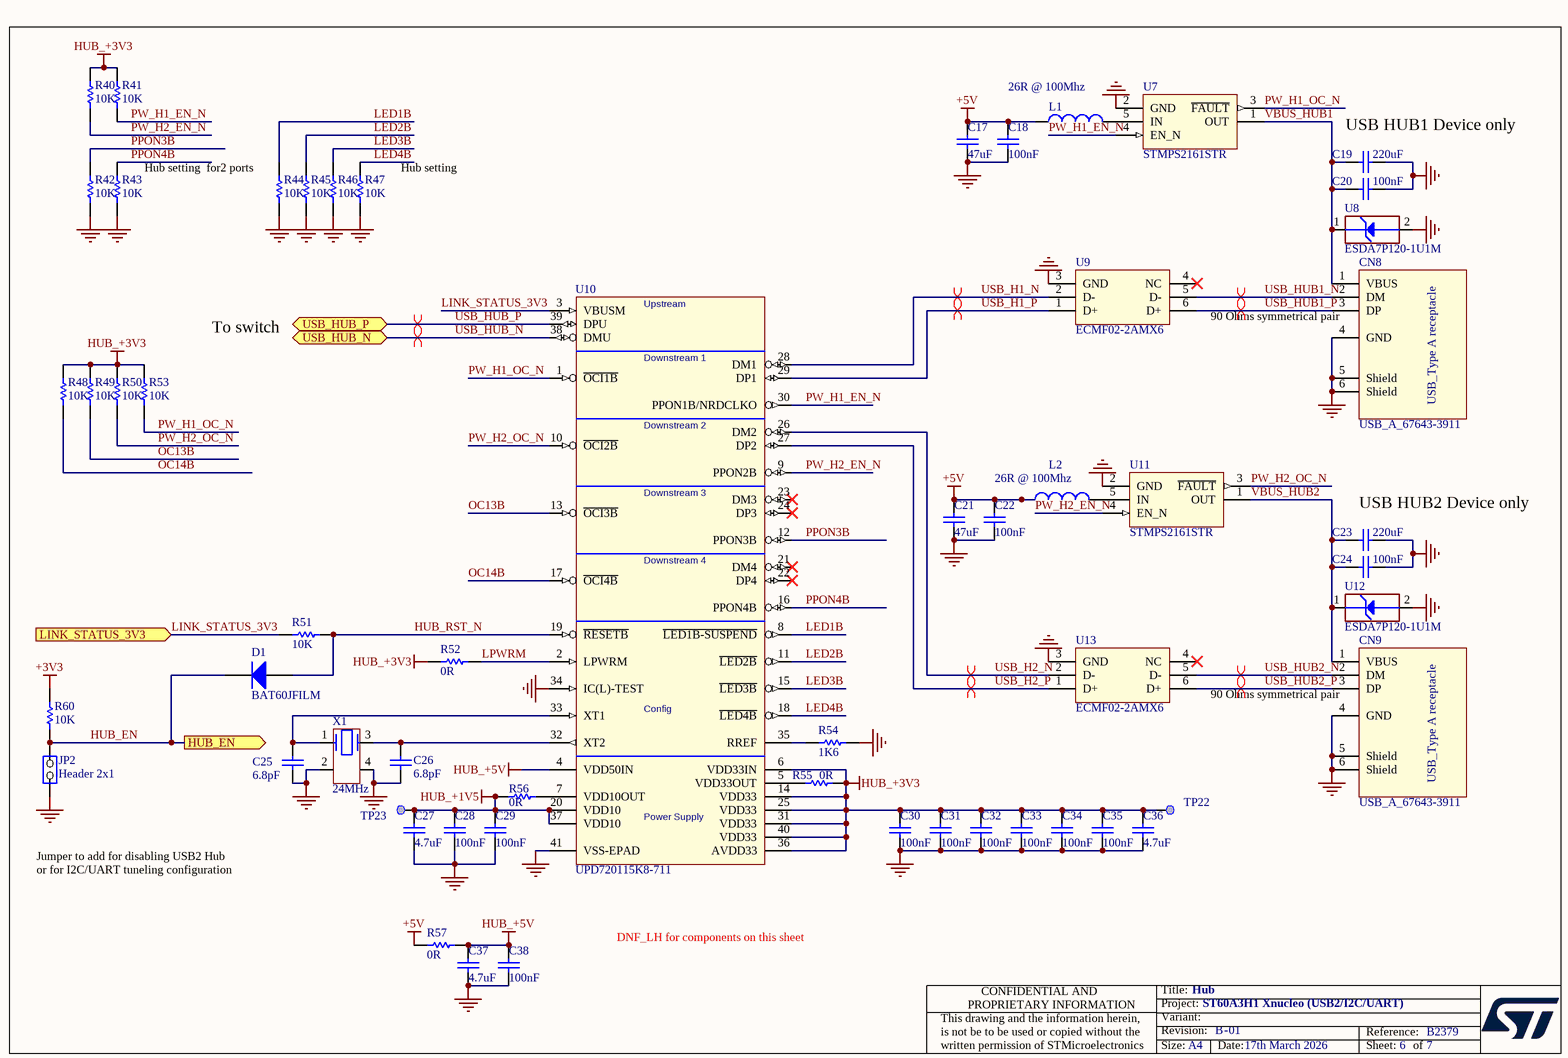
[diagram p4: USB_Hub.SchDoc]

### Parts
C17  value 47uF  [C0805]  (hidden comment: Capacitor)
C18  value 100nF  [C0402]  (hidden comment: Capacitor)
C19  value 220uF  [C1206_H1P6]  (hidden comment: Capacitor)
C20  value 100nF  [C0402]  (hidden comment: Capacitor)
C21  value 47uF  [C0805]  (hidden comment: Capacitor)
C22  value 100nF  [C0402]  (hidden comment: Capacitor)
C23  value 220uF  [C1206_H1P6]  (hidden comment: Capacitor)
C24  value 100nF  [C0402]  (hidden comment: Capacitor)
C25  value 6.8pF  [C0402]  (hidden comment: Capacitor)
C26  value 6.8pF  [C0402]  (hidden comment: Capacitor)
C27  value 4.7uF  [C0402]  (hidden comment: Capacitor)
C28  value 100nF  [C0402]  (hidden comment: Capacitor)
C29  value 100nF  [C0402]  (hidden comment: Capacitor)
C30  value 100nF  [C0402]  (hidden comment: Capacitor)
C31  value 100nF  [C0402]  (hidden comment: Capacitor)
C32  value 100nF  [C0402]  (hidden comment: Capacitor)
C33  value 100nF  [C0402]  (hidden comment: Capacitor)
C34  value 100nF  [C0402]  (hidden comment: Capacitor)
C35  value 100nF  [C0402]  (hidden comment: Capacitor)
C36  value 4.7uF  [C0402]  (hidden comment: Capacitor)
C37  value 4.7uF  [C0402]  (hidden comment: Capacitor)
C38  value 100nF  [C0402]  (hidden comment: Capacitor)
CN8  value USB_A_67643-3911  [CON_USB-TYPEA_MOLEX_67643-3911_H7P73]  (hidden comment: USB_TypeA_Receptacle_67643-3911)
CN9  value USB_A_67643-3911  [CON_USB-TYPEA_MOLEX_67643-3911_H7P73]  (hidden comment: USB_TypeA_Receptacle_67643-3911)
D1  BAT60JFILM  [DIO_SOD323]
JP2  value Header 2x1  [CON_SAMTEC_TSW-102-07-G-S]  (hidden comment: Jumper_Header 2x1)
L1  value 26R @ 100Mhz  [FIL_0603_H0P65]  (hidden comment: BEAD)
L2  value 26R @ 100Mhz  [FIL_0603_H0P65]  (hidden comment: BEAD)
R40  value 10K  [R0402]  (hidden comment: Resistor)
R41  value 10K  [R0402]  (hidden comment: Resistor)
R42  value 10K  [R0402]  (hidden comment: Resistor)
R43  value 10K  [R0402]  (hidden comment: Resistor)
R44  value 10K  [R0402]  (hidden comment: Resistor)
R45  value 10K  [R0402]  (hidden comment: Resistor)
R46  value 10K  [R0402]  (hidden comment: Resistor)
R47  value 10K  [R0402]  (hidden comment: Resistor)
R48  value 10K  [R0402]  (hidden comment: Resistor)
R49  value 10K  [R0402]  (hidden comment: Resistor)
R50  value 10K  [R0402]  (hidden comment: Resistor)
R51  value 10K  [R0402]  (hidden comment: Resistor)
R52  value 0R  [R0402]  (hidden comment: Resistor)
R53  value 10K  [R0402]  (hidden comment: Resistor)
R54  value 1K6  [R0402]  (hidden comment: Resistor)
R55  value 0R  [R0402]  (hidden comment: Resistor)
R56  value 0R  [R0402]  (hidden comment: Resistor)
R57  value 0R  [R0402]  (hidden comment: Resistor)
R60  value 10K  [R0402]  (hidden comment: Resistor)
TP22  Test Point  [TP_SMD_1MM]  (value not drawn)  (no BOM)
TP23  Test Point  [TP_SMD_1MM]  (value not drawn)  (no BOM)
U7  STMPS2161STR  [MOS_SOT23-5L]
U8  value ESDA7P120-1U1M  [ESD_QFN1610_2N_1K_2A]  (hidden comment: ​Footprint needed DFN105P160X60-2N)
U9  value ECMF02-2AMX6  [ESD_QFN-6L_1P7X1P5_P050]  (hidden comment: ​)
U10  value UPD720115K8-711  [ICC_QFN40-EPAD_6X6_P050]  (hidden comment: UPD720115)
U11  STMPS2161STR  [MOS_SOT23-5L]
U12  value ESDA7P120-1U1M  [ESD_QFN1610_2N_1K_2A]  (hidden comment: ​Footprint needed DFN105P160X60-2N)
U13  value ECMF02-2AMX6  [ESD_QFN-6L_1P7X1P5_P050]  (hidden comment: ​)
X1  value 24MHz  [CRY_NX2016SA_4P]  (hidden comment: XTAL_4_PINS)

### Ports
HUB_EN (out), LINK_STATUS_3V3 (in), USB_HUB_N (bidir), USB_HUB_P (bidir)

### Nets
+3V3: R60.2
+5V: C17.2 C18.2 C21.2 C22.2 L1.1 L2.1 R57.1
GND: C17.1 C18.1 C19.1 C20.1 C21.1 C22.1 C23.1 C24.1 C25.1 C26.1 C27.1 C28.1 C29.1 C30.1 C31.1 C32.1 C33.1 C34.1 C35.1 C36.1 C37.1 C38.1 CN8.4(GND) CN8.5(Shield) CN8.6(Shield) CN9.4(GND) CN9.5(Shield) CN9.6(Shield) JP2.1(COMMON) R42.1 R43.1 R44.1 R45.1 R46.1 R47.1 R54.2 U7.2(GND) U8.2(GND) U9.3(GND) U10.34(IC(L)-TEST) U10.41(VSS-EPAD) U11.2(GND) U12.2(GND) U13.3(GND) X1.2 X1.4
HUB_+1V5: C27.2 C28.2 C29.2 R56.1 TP23.1 U10.20(VDD10) U10.37(VDD10)
HUB_+3V3: C30.2 C31.2 C32.2 C33.2 C34.2 C35.2 C36.2 R40.2 R41.2 R48.2 R49.2 R50.2 R52.1 R53.2 R55.2 TP22.1 U10.6(VDD33IN) U10.14(VDD33) U10.25(VDD33) U10.31(VDD33) U10.36(AVDD33) U10.40(VDD33)
HUB_+5V: C37.2 C38.2 R57.2 U10.4(VDD50IN)
HUB_EN: D1.2(K) JP2.2(NO) R60.1 ; port HUB_EN
HUB_RST_N: D1.1(A) R51.2 U10.19(~{RESETB})  [project net HUB_RST_N_6]
LED1B: R44.2 U10.8(~{LED1B-SUSPEND})  [project net LED1B_6]
LED2B: R45.2 U10.11(~{LED2B})  [project net LED2B_6]
LED3B: R46.2 U10.15(~{LED3B})  [project net LED3B_6]
LED4B: R47.2 U10.18(~{LED4B})  [project net LED4B_6]
LINK_STATUS_3V3: R51.1 U10.3(VBUSM) ; port LINK_STATUS_3V3
LPWRM: R52.2 U10.2(LPWRM)  [project net LPWRM_6]
OC13B: R49.1 U10.13(~{OCI3B})  [project net OC13B_6]
OC14B: R48.1 U10.17(~{OCI4B})  [project net OC14B_6]
PPON3B: R42.2 U10.12(PPON3B)  [project net PPON3B_6]
PPON4B: R43.2 U10.16(PPON4B)  [project net PPON4B_6]
PW_H1_EN_N: R41.1 U7.4(EN_N) U10.30(PPON1B/NRDCLKO)  [project net PW_H1_EN_N_6]
PW_H1_OC_N: R53.1 U7.3(~{FAULT}) U10.1(~{OCI1B})  [project net PW_H1_OC_N_6]
PW_H2_EN_N: R40.1 U10.9(PPON2B) U11.4(EN_N)  [project net PW_H2_EN_N_6]
PW_H2_OC_N: R50.1 U10.10(~{OCI2B}) U11.3(~{FAULT})  [project net PW_H2_OC_N_6]
USB_H1_N: U9.2(D-) U10.28(DM1)  [project net USB_H1_N_6]
USB_H1_P: U9.1(D+) U10.29(DP1)  [project net USB_H1_P_6]
USB_H2_N: U10.26(DM2) U13.2(D-)  [project net USB_H2_N_6]
USB_H2_P: U10.27(DP2) U13.1(D+)  [project net USB_H2_P_6]
USB_HUB1_N: CN8.2(DM) U9.5(D-)  [project net USB_HUB1_N_6]
USB_HUB1_P: CN8.3(DP) U9.6(D+)  [project net USB_HUB1_P_6]
USB_HUB2_N: CN9.2(DM) U13.5(D-)  [project net USB_HUB2_N_6]
USB_HUB2_P: CN9.3(DP) U13.6(D+)  [project net USB_HUB2_P_6]
USB_HUB_N: U10.38(DMU) ; port USB_HUB_N
USB_HUB_P: U10.39(DPU) ; port USB_HUB_P
VBUS_HUB1: C19.2 C20.2 CN8.1(VBUS) U7.1(OUT) U8.1(IO1)  [project net VBUS_HUB1_6]
VBUS_HUB2: C23.2 C24.2 CN9.1(VBUS) U11.1(OUT) U12.1(IO1)  [project net VBUS_HUB2_6]
NetC25_2: C25.2 U10.33(XT1) X1.1
NetC26_2: C26.2 U10.32(XT2) X1.3
NetL1_2: L1.2 U7.5(IN)
NetL2_2: L2.2 U11.5(IN)
NetR54_1: R54.1 U10.35(RREF)
NetR55_1: R55.1 U10.5(VDD33OUT)
NetR56_2: R56.2 U10.7(VDD10OUT)

Not connected (* = marked no-connect by the designer): U9 4(NC)*; U10 21(DM4)* 22(DP4)* 23(DM3)* 24(DP3)*; U13 4(NC)*

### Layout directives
differential pair; differential pair class 90 Ohms  Zdiff; rule Differential Pairs Routing [Pref Gap = 0.127mm    Min Gap  = 0.127mm    Max Gap  = 0.127mmPref Width = 0.19mm    Min Width  = 0.19mm    Max Width  = 0.19mm]: USB_H1_N_6, USB_H1_P_6, USB_H2_N_6, USB_H2_P_6, USB_HUB1_N_6, USB_HUB1_P_6, USB_HUB2_N_6, USB_HUB2_P_6, USB_HUB_N, USB_HUB_P

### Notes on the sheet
- (near C19) USB HUB1 Device only
- (near R44) Hub setting  for2 ports
- (near R47) Hub setting
- To switch
- (near CN8) 90 Ohms symmetrical pair
- (near C23) USB HUB2 Device only
- (near CN9) 90 Ohms symmetrical pair
- Jumper to add for disabling USB2 Hub
- or for I2C/UART tuneling configuration
- DNF_LH for components on this sheet

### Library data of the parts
C17 C21 = MCD-00204: Capacitor, MLCC, 47uF, 10V, X5R, +/-20%, 0805, T=1.25mm; Manufacturer_Part_Number: GRM21BR61A476ME15K; Manufacturer: MURATA; Part_Preference: Recommended; Component_Country_Of_Origin: Japan°°; ShowFields: YES; ID: 2664
C18 C20 C22 C24 C28-C35 C38 = MCD-00006: Capacitor, MLCC, 100nF, 16V, X7R, +/-10%, 0402, T=0.5mm; Manufacturer_Part_Number: CC0402KRX7R7BB104; Manufacturer: YAGEO; Part_Preference: Recommended; Partial_Alternate_Internal_Part_Number: MCD-03299; Order_Code_RS: 9402047; Component_Country_Of_Origin: China; ShowFields: YES; ID: 2474
C19 C23 = MCD-00104: Capacitor, MLCC, 220uF, 6V3, X5R, +/-20%, 1206, T=1.6mm; Manufacturer_Part_Number: GRM31CR60J227ME11; Manufacturer: MURATA; Part_Preference: Recommended; Order_Code_RS: 170-6396; Component_Country_Of_Origin: Japan°°; ShowFields: YES; ID: 2764
C25 C26 = MCD-00674: Capacitor, MLCC, 6.8pF, 50V, NPO, +/-0.25pF, 0402, T=0.5mm; Manufacturer_Part_Number: CC0402CRNPO9BN6R8; Manufacturer: YAGEO; Part_Preference: Recommended; Component_Country_Of_Origin: China; ShowFields: YES; ID: 3068
C27 C36 C37 = MCD-01356: Capacitor, MLCC, 4.7uF, 6V3, X5R, +/-20%, 0402, T=0.5mm; Manufacturer_Part_Number: GRM155R60J475ME47; Manufacturer: MURATA; Part_Preference: Recommended; Order_Code_RS: 814-5230; Component_Country_Of_Origin: Japan°°; ShowFields: YES; ID: 3456
CN8 CN9 = MCD-01475: USB_TypeA, RA, TH, T= 7.73mm (USB certified); Part_Type: Connector; Part_Preference: Recommended; Manufacturer: MOLEX; Order_Code_RS: 800-6879; Component_Country_Of_Origin: Unknown; ShowFields: YES; ID: 3575
D1 = MCD-00034: Diode, Schottky, 0V53, 1A, 10V, SOD323; BMS_Part_Number: 9151097; Part_Preference: Recommended; Manufacturer: STMICROELECTRONICS; Manufacturer_HQ_COO: EU; Order_Code_RS: 714-6879; Component_Country_Of_Origin: China; ShowFields: YES; ID: 2483
JP2 = MCD-00045: as JP1 on sheet NUCLEO
L1 L2 = MCD-00305: Ferrite bead, 26R @ 100Mhz, +/-25%, 6000mA, 0R007, 0603, T=0.75mm; Manufacturer_Part_Number: BLM18KG260TN1; Manufacturer: MURATA; Part_Type: Inductor; Part_Preference: Recommended; Order_Code_RS: 747-4723; Component_Country_Of_Origin: Japan°°; ShowFields: YES; ID: 2564
R40-R51 R53 R60 = MCD-00053: as R34 on sheet ST60A3H1
R52 R55-R57 = MCD-00052: as R18 on sheet ST60A3H1
R54 = MCD-00401: Resistor, 1K6, 0402, +/-1%, 1/16W; Part_Preference: Recommended; Manufacturer: YAGEO; Manufacturer_Part_Number: RC0402FR-071K6L; Component_Country_Of_Origin: China; ShowFields: YES; ID: 2877
TP22 TP23 = MCD-00074: as TP19 on sheet ST60A3H1
U7 U11 = MCD-01167: Switch, Enhanced single channel power switches; BMS_Part_Number: 9159017; Part_Type: IC; Part_Preference: Recommended; Manufacturer: STMICROELECTRONICS; Manufacturer_HQ_COO: EU; Order_Code_RS: 110-6370; Component_Country_Of_Origin: Malaysia; ShowFields: YES; ID: 3330
U8 U12 = MCD-01026: Diode, ESD TVS, 5V5, 1.5uA, 6V8, QFN1610; Manufacturer: STMICROELECTRONICS; BMS_Part_Number: 9179046; Part_Preference: Recommended; Manufacturer_HQ_COO: EU; Order_Code_RS: 190-7605; Component_Country_Of_Origin: China; ShowFields: YES; ID: 2997
U9 U13 = MCD-00649: as U6 on sheet ST60A3H1
U10 = MCD-03908: IC, USB 2.0, 4 ports, Hi-Speed hub controller, -40° To +85°; Part_Preference: Recommended; Manufacturer: RENESAS ELECTRONICS; ShowFields: YES; ID: 6024; Component_Country_Of_Origin: Unknown
X1 = MCD-01036: Crystal, 24MHz, 6pF, +/-20ppm, 80R, 2x1.6mm; Part_Type: Crystal_Osc; Manufacturer_Part_Number: NX2016SA-24MHZ-EXS00A-CS10820; Manufacturer: NDK; BMS_Part_Number: 9157045; Part_Preference: Recommended; Component_Country_Of_Origin: Unknown; ShowFields: YES; ID: 2989

## Sheet LEGAL_DISCLAIMER.SchDoc: LEGAL_DISCLAIMER
size A4; Date: Not used; ApprovedBy: Not used; CheckedBy: Not used; Author: Not used; CompanyName: STMicroelectronics; DrawnBy: Not used; Engineer: Not used; Organization: Not used; Address1: Not used; Address2: Not used; Address3: Not used; Address4: Not used; DocumentNumber: 7; Revision: Not used; SheetNumber: 7; SheetTotal: 7
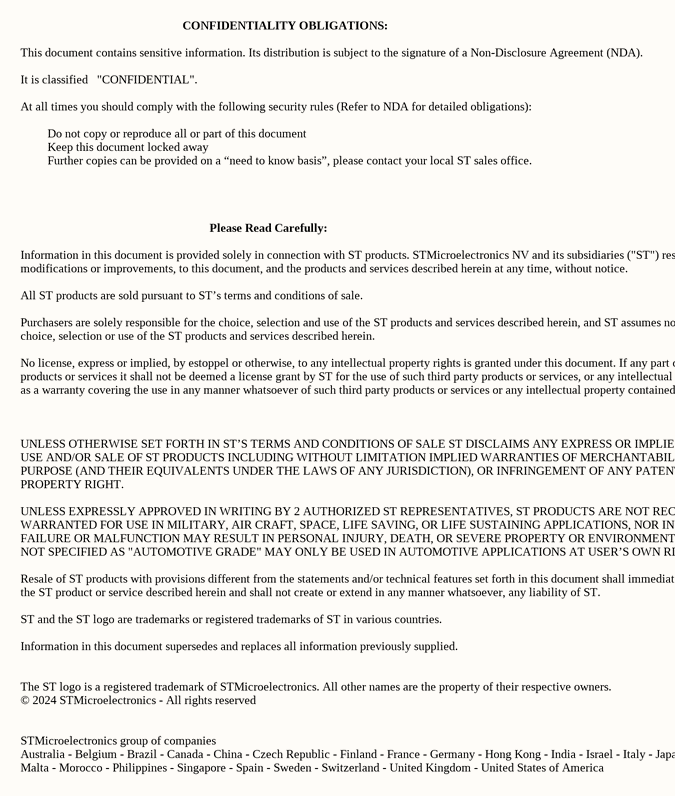
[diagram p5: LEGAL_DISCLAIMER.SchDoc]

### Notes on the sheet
- This document contains sensitive information. Its distribution is subject to the signature of a Non-Disclosure Agreement (NDA).
- It is classified   "CONFIDENTIAL".
- CONFIDENTIALITY OBLIGATIONS:
- At all times you should comply with the following security rules (Refer to NDA for detailed obligations):
- Do not copy or reproduce all or part of this document
- Keep this document locked away
- Further copies can be provided on a “need to know basis”, please contact your local ST sales office.
- Information in this document is provided solely in connection with ST products. STMicroelectronics NV and its subsidiaries ("ST") reserve the right to make changes, corrections,
- modifications or improvements, to this document, and the products and services described herein at any time, without notice.
- Please Read Carefully:
- All ST products are sold pursuant to ST’s terms and conditions of sale.
- Purchasers are solely responsible for the choice, selection and use of the ST products and services described herein, and ST assumes no liability whatsoever relating to the
- choice, selection or use of the ST products and services described herein.
- No license, express or implied, by estoppel or otherwise, to any intellectual property rights is granted under this document. If any part of this document refers to any third party
- products or services it shall not be deemed a license grant by ST for the use of such third party products or services, or any intellectual property contained therein or considered
- as a warranty covering the use in any manner whatsoever of such third party products or services or any intellectual property contained therein.
- UNLESS OTHERWISE SET FORTH IN ST’S TERMS AND CONDITIONS OF SALE ST DISCLAIMS ANY EXPRESS OR IMPLIED WARRANTY WITH RESPECT TO THE
- USE AND/OR SALE OF ST PRODUCTS INCLUDING WITHOUT LIMITATION IMPLIED WARRANTIES OF MERCHANTABILITY, FITNESS FOR A PARTICULAR
- PURPOSE (AND THEIR EQUIVALENTS UNDER THE LAWS OF ANY JURISDICTION), OR INFRINGEMENT OF ANY PATENT, COPYRIGHT OR OTHER INTELLECTUAL
- PROPERTY RIGHT.
- UNLESS EXPRESSLY APPROVED IN WRITING BY 2 AUTHORIZED ST REPRESENTATIVES, ST PRODUCTS ARE NOT RECOMMENDED, AUTHORIZED OR
- WARRANTED FOR USE IN MILITARY, AIR CRAFT, SPACE, LIFE SAVING, OR LIFE SUSTAINING APPLICATIONS, NOR IN PRODUCTS OR SYSTEMS WHERE
- FAILURE OR MALFUNCTION MAY RESULT IN PERSONAL INJURY, DEATH, OR SEVERE PROPERTY OR ENVIRONMENTAL DAMAGE. ST PRODUCTS WHICH ARE
- NOT SPECIFIED AS "AUTOMOTIVE GRADE" MAY ONLY BE USED IN AUTOMOTIVE APPLICATIONS AT USER’S OWN RISK.
- Resale of ST products with provisions different from the statements and/or technical features set forth in this document shall immediately void any warranty granted by ST for
- the ST product or service described herein and shall not create or extend in any manner whatsoever, any liability of ST.
- ST and the ST logo are trademarks or registered trademarks of ST in various countries.
- Information in this document supersedes and replaces all information previously supplied.
- The ST logo is a registered trademark of STMicroelectronics. All other names are the property of their respective owners.
- © 2024 STMicroelectronics - All rights reserved
- STMicroelectronics group of companies
- Australia - Belgium - Brazil - Canada - China - Czech Republic - Finland - France - Germany - Hong Kong - India - Israel - Italy - Japan - Malaysia -
- Malta - Morocco - Philippines - Singapore - Spain - Sweden - Switzerland - United Kingdom - United States of America

## Sheet Switch.SchDoc: SWITCH
size A4; Project: STM32MP15-DISCO PI; Date: Not used; ApprovedBy: Not used; CheckedBy: Not used; Author: Not used; CompanyName: STMicroelectronics; DrawnBy: Not used; Engineer: Not used; Organization: Not used; Address1: Not used; Address2: Not used; Address3: Not used; Address4: Not used; DocumentNumber: 5; Revision: Not used; SheetNumber: 5; SheetTotal: 7
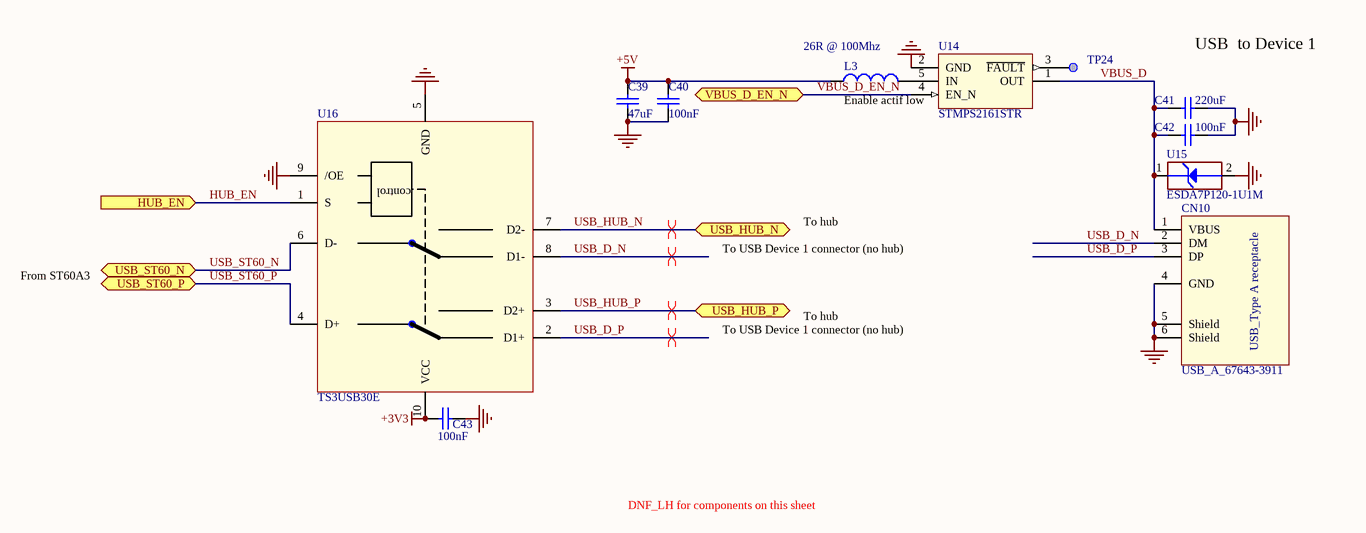
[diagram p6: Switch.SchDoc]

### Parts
C39  value 47uF  [C0805]  (hidden comment: Capacitor)
C40  value 100nF  [C0402]  (hidden comment: Capacitor)
C41  value 220uF  [C1206_H1P6]  (hidden comment: Capacitor)
C42  value 100nF  [C0402]  (hidden comment: Capacitor)
C43  value 100nF  [C0402]  (hidden comment: Capacitor)
CN10  value USB_A_67643-3911  [CON_USB-TYPEA_MOLEX_67643-3911_H7P73]  (hidden comment: USB_TypeA_Receptacle_67643-3911)
L3  value 26R @ 100Mhz  [FIL_0603_H0P65]  (hidden comment: BEAD)
TP24  Test Point  [TP_SMD_1MM]  (value not drawn)  (no BOM)
U14  STMPS2161STR  [MOS_SOT23-5L]
U15  value ESDA7P120-1U1M  [ESD_QFN1610_2N_1K_2A]  (hidden comment: ​Footprint needed DFN105P160X60-2N)
U16  TS3USB30E  [ICC_VSSOP10_3X3_P050]

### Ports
HUB_EN (in), USB_HUB_N (bidir), USB_HUB_P (bidir), USB_ST60_N (bidir), USB_ST60_P (bidir), VBUS_D_EN_N (bidir)

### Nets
+3V3: C43.2 U16.10(VCC)
+5V: C39.2 C40.2 L3.1
GND: C39.1 C40.1 C41.1 C42.1 C43.1 CN10.4(GND) CN10.5(Shield) CN10.6(Shield) U14.2(GND) U15.2(GND) U16.5(GND) U16.9(/OE)
HUB_EN: U16.1(S) ; port HUB_EN
USB_D_N: CN10.2(DM) U16.8(D1-)  [project net USB_D_N_5]
USB_D_P: CN10.3(DP) U16.2(D1+)  [project net USB_D_P_5]
USB_HUB_N: U16.7(D2-) ; port USB_HUB_N
USB_HUB_P: U16.3(D2+) ; port USB_HUB_P
USB_ST60_N: U16.6(D-) ; port USB_ST60_N
USB_ST60_P: U16.4(D+) ; port USB_ST60_P
VBUS_D: C41.2 C42.2 CN10.1(VBUS) U14.1(OUT) U15.1(IO1)  [project net VBUS_D_5]
VBUS_D_EN_N: U14.4(EN_N) ; port VBUS_D_EN_N
NetL3_2: L3.2 U14.5(IN)
NetTP24_1: TP24.1 U14.3(~{FAULT})

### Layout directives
differential pair; differential pair class 90 Ohms  Zdiff; rule Differential Pairs Routing [Pref Gap = 0.127mm    Min Gap  = 0.127mm    Max Gap  = 0.127mmPref Width = 0.19mm    Min Width  = 0.19mm    Max Width  = 0.19mm]: USB_D_N_5, USB_D_P_5, USB_HUB_N, USB_HUB_P

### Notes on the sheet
- USB  to Device 1
- (near U14) Enable actif low
- To USB Device 1 connector (no hub)
- To hub
- From ST60A3
- DNF_LH for components on this sheet

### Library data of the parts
C39 = MCD-00204: as C17 on sheet USB_Hub
C40 C42 C43 = MCD-00006: as C18 on sheet USB_Hub
C41 = MCD-00104: as C19 on sheet USB_Hub
CN10 = MCD-01475: as CN8 on sheet USB_Hub
L3 = MCD-00305: as L1 on sheet USB_Hub
TP24 = MCD-00074: as TP19 on sheet ST60A3H1
U14 = MCD-01167: as U7 on sheet USB_Hub
U15 = MCD-01026: as U8 on sheet USB_Hub
U16 = MCD-02208: USB Switch, ESD-Protected, High-Speed USB 2.0, 480Mbit/s, 1:2 Multiplexer/Demultiplexer switch with single enable; Part_Type: IC; Part_Preference: Recommended; Manufacturer: TEXAS INSTRUMENTS; Value: TS3USB30EDGSR; Order_Code_RS: 162-8445; Component_Country_Of_Origin: Thailand; ShowFields: YES; ID: 4308

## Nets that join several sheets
+1V8: ST60A3H1 (8 pins), NUCLEO (7 pins)
+3V3: ST60A3H1 (R16.2 R18.2), NUCLEO (17 pins), USB_Hub (R60.2), Switch (C43.2 U16.10)
+5V: ST60A3H1 (C10.2 R14.2 TP18.1), NUCLEO (5 pins), USB_Hub (7 pins), Switch (C39.2 C40.2 L3.1)
GND: ST60A3H1 (32 pins), NUCLEO (24 pins), USB_Hub (46 pins), Switch (12 pins)
HUB_EN: USB_Hub (D1.2 JP2.2 R60.1), Switch (U16.1)
LINK_STATUS_1V8: ST60A3H1 (R34.2 R38.2 U4.J1 U5.5), NUCLEO (U3.12)
LINK_STATUS_3V3: NUCLEO (U3.9), USB_Hub (R51.1 U10.3)
MODE_INT_1V8: ST60A3H1 (U4.G1), NUCLEO (U3.6)
RF_EN_1V8: ST60A3H1 (U4.H1), NUCLEO (R3.2 R33.2)
RX_GPIO1_1V8: ST60A3H1 (R37.1 U4.D1), NUCLEO (U3.16)
SCL_1V8: ST60A3H1 (R25.1 R26.1), NUCLEO (JP5.1 U3.2)
SCL_GPIO2_1V8: ST60A3H1 (R36.1 U4.K1), NUCLEO (JP5.2)
SDA_1V8: ST60A3H1 (R23.1 R27.1), NUCLEO (JP6.1 U3.18)
SDA_GPIO3_1V8: ST60A3H1 (R35.1 U4.M2), NUCLEO (JP6.2)
TX_GPIO0_1V8: ST60A3H1 (R39.1 U4.B2), NUCLEO (U3.4)
USB_HUB_N: USB_Hub (U10.38), Switch (U16.7)
USB_HUB_P: USB_Hub (U10.39), Switch (U16.3)
USB_ST60_N: ST60A3H1 (R32.1), Switch (U16.6)
USB_ST60_P: ST60A3H1 (R31.1), Switch (U16.4)
VBUS_D_EN_N: ST60A3H1 (LD1.2 Q1.3), Switch (U14.4)

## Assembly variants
LOCAL: not fitted C17 C18 C19 C20 C21 C22 C23 C24 C25 C26 C27 C28 C29 C30 C31 C32 C33 C34 C35 C36 C37 C38 C39 C40 C41 C42 C43 CN8 CN9 CN10 D1 JP2 L1 L2 L3 R2 R3 R8 R9 R10 R11 R12 R17 R20 R28 R31 R32 R35 R36 R37 R39 R40 R41 R42 R43 R44 R45 R46 R47 R48 R49 R50 R51 R52 R53 R54 R55 R56 R57 R58 R59 R60 R62 U7 U8 U9 U10 U11 U12 U13 U14 U15 U16 X1
REMOTE: not fitted R2 R8 R9 R10 R11 R12 R17 R20 R22 R26 R27 R29 R30 R33 R35 R36 R37 R39 R58 R59 R61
